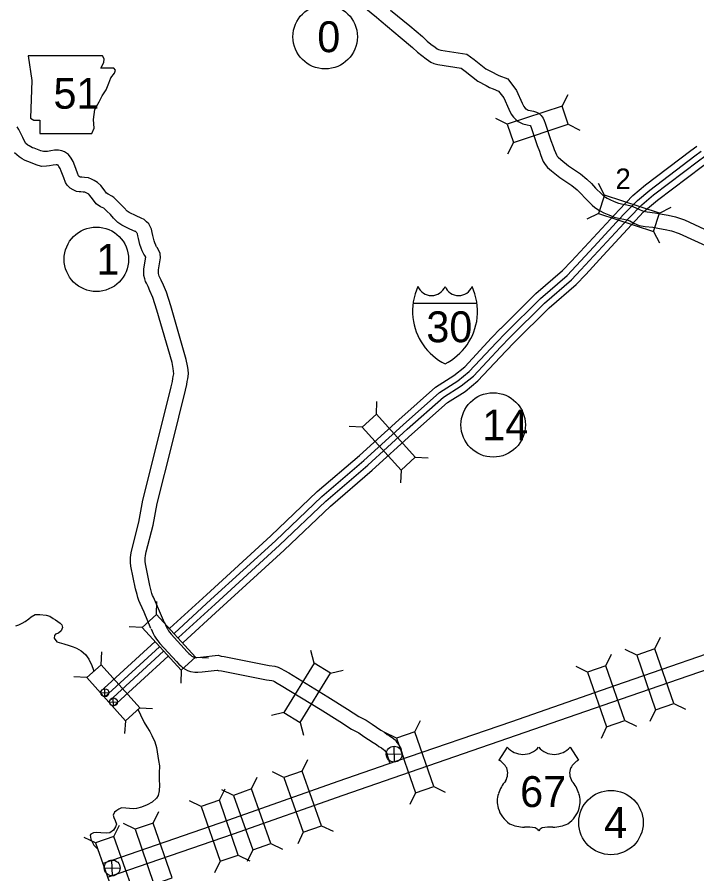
# Model space of a CAD drawing. Extents: x 1369979 to 1371646, y 379997 to 381064.
# Drawn here: x 1370115.6 to 1370224.5, y 380672.1 to 380809.4 of the extents above; entities that cross this region are included whole.
import ezdxf

# ---------------------------------------------------------------- set-up
doc = ezdxf.new("R2010")
doc.units = 0
doc.layers.add('R_Border Notes', color=7, linetype='Continuous')

msp = doc.modelspace()

# ---------------------------------------------------------------- linework, layer by layer
at = {"layer": 'R_Border Notes'}
for p, q in [((1370202.9, 380795.11), (1370203.82, 380796.96)), ((1370194.09, 380792.19), (1370192.25, 380793.11)), ((1370203.87, 380792.18), (1370205.72, 380791.25)), ((1370195.07, 380789.25), (1370194.14, 380787.41)), ((1370209.66, 380780.84), (1370208.72, 380782.68)), ((1370208.69, 380777.9), (1370206.85, 380776.96)), ((1370218.48, 380777.95), (1370220.32, 380778.88)), ((1370217.51, 380775.01), (1370218.45, 380773.17)), ((1370179, 380763.5), (1370189.24, 380763.5)), ((1370173.12, 380745.73), (1370173.22, 380747.79)), ((1370170.83, 380743.66), (1370168.77, 380743.76)), ((1370179.36, 380738.86), (1370181.42, 380738.76)), ((1370177.07, 380736.78), (1370176.97, 380734.72)), ((1370137.88, 380713.64), (1370137.97, 380715.7)), ((1370135.6, 380711.54), (1370133.53, 380711.63)), ((1370217.74, 380708.13), (1370218.65, 380709.99)), ((1370163.14, 380705.85), (1370162.65, 380707.86)), ((1370214.82, 380707.12), (1370212.97, 380708.03)), ((1370129.04, 380705.59), (1370129.16, 380707.65)), ((1370144.15, 380706.79), (1370146.21, 380706.7)), ((1370209.88, 380705.42), (1370210.78, 380707.27)), ((1370206.96, 380704.4), (1370205.1, 380705.3)), ((1370126.73, 380703.53), (1370124.67, 380703.64)), ((1370141.87, 380704.7), (1370141.78, 380702.64)), ((1370165.78, 380704.24), (1370167.78, 380704.73)), ((1370129, 380701.08), (1370130.27, 380701.11)), ((1370129.65, 380700.46), (1370129.62, 380701.73)), ((1370130.36, 380699.6), (1370131.63, 380699.63)), ((1370131.01, 380698.98), (1370130.98, 380700.25)), ((1370135.22, 380698.67), (1370137.28, 380698.55)), ((1370217.85, 380698.35), (1370216.95, 380696.5)), ((1370220.77, 380699.36), (1370222.63, 380698.46)), ((1370158.3, 380697.93), (1370156.3, 380697.45)), ((1370179.28, 380694.82), (1370180.19, 380696.67)), ((1370132.92, 380696.61), (1370132.8, 380694.55)), ((1370160.94, 380696.32), (1370161.43, 380694.32)), ((1370210, 380695.63), (1370209.11, 380693.78)), ((1370212.93, 380696.65), (1370214.78, 380695.75)), ((1370176.36, 380693.81), (1370174.5, 380694.71)), ((1370174.7, 380691.23), (1370177.25, 380691.29)), ((1370176.01, 380689.99), (1370175.95, 380692.53)), ((1370194.09, 380692.38), (1370192.74, 380690.29)), ((1370204.15, 380692.38), (1370205.5, 380690.29)), ((1370161.24, 380688.54), (1370162.13, 380690.4)), ((1370153.14, 380685.68), (1370154.03, 380687.54)), ((1370158.32, 380687.51), (1370156.46, 380688.4)), ((1370147.98, 380683.86), (1370148.89, 380685.72)), ((1370182.31, 380686.05), (1370184.16, 380685.14)), ((1370150.22, 380684.65), (1370148.36, 380685.54)), ((1370179.39, 380685.04), (1370178.48, 380683.18)), ((1370145.06, 380682.86), (1370143.2, 380683.76)), ((1370137.39, 380680.22), (1370138.29, 380682.07)), ((1370131.08, 380678.04), (1370131.97, 380679.9)), ((1370134.46, 380679.21), (1370132.61, 380680.12)), ((1370164.33, 380679.79), (1370166.19, 380678.9)), ((1370128.15, 380677.02), (1370126.3, 380677.92)), ((1370161.41, 380678.76), (1370160.52, 380676.9)), ((1370156.22, 380676.93), (1370158.09, 380676.04)), ((1370151, 380675.09), (1370152.85, 380674.18)), ((1370153.31, 380675.9), (1370152.42, 380674.04)), ((1370130.83, 380671.75), (1370130.77, 380674.29)), ((1370148.08, 380674.08), (1370147.17, 380672.23)), ((1370129.53, 380672.99), (1370132.07, 380673.05))]:
    msp.add_line(p, q, dxfattribs=at)
for points in [[(1370170.57, 380811.45), (1370173.14, 380809.33), (1370173.91, 380808.69), (1370176.96, 380806.16), (1370178.93, 380804.51), (1370179.72, 380803.75), (1370180.42, 380803.19), (1370181.12, 380802.66), (1370181.47, 380802.4), (1370181.82, 380802.14), (1370182.31, 380801.94), (1370182.96, 380801.75), (1370186.68, 380801.2), (1370187.35, 380800.7), (1370189.4, 380799.09), (1370190.72, 380798.41), (1370191.26, 380798.1), (1370191.85, 380797.85), (1370192.71, 380797.51)], [(1370175.41, 380810.49), (1370178.46, 380807.96), (1370180.49, 380806.26), (1370181.27, 380805.51), (1370181.86, 380805.04), (1370182.53, 380804.53), (1370182.87, 380804.28), (1370182.98, 380804.2), (1370183.09, 380804.15), (1370183.46, 380804.05), (1370187.6, 380803.43), (1370188.77, 380802.56), (1370190.67, 380801.07), (1370191.84, 380800.48), (1370192.31, 380800.2), (1370192.75, 380800.02), (1370194.18, 380799.45)], [(1370194.18, 380799.45), (1370195.57, 380797.6), (1370196.46, 380795.59), (1370196.73, 380795.04), (1370196.88, 380794.84), (1370197.03, 380794.68), (1370197.09, 380794.64), (1370197.44, 380794.45), (1370197.75, 380794.37), (1370198.3, 380794.28), (1370198.77, 380794.13), (1370199.18, 380793.91), (1370199.53, 380793.59), (1370199.84, 380793.16), (1370200.01, 380792.81), (1370200.15, 380792.39), (1370201.07, 380789.59), (1370201.45, 380788.65), (1370201.6, 380788.16), (1370201.81, 380787.65), (1370201.96, 380787.29), (1370202.09, 380787.07), (1370202.23, 380786.9), (1370202.67, 380786.52), (1370203.88, 380785.54), (1370205.83, 380784.25), (1370206.85, 380783.41), (1370207.57, 380782.71), (1370208.24, 380781.96), (1370209.26, 380780.98), (1370209.58, 380780.69), (1370210.07, 380780.36), (1370210.54, 380780.11), (1370211.21, 380779.84), (1370211.92, 380779.56), (1370212.63, 380779.4), (1370213.26, 380779.29), (1370213.96, 380779.12), (1370214.69, 380778.81), (1370215.36, 380778.46), (1370215.9, 380778.24), (1370216.51, 380778.14), (1370217.75, 380778.01), (1370218.9, 380777.81), (1370219.87, 380777.61), (1370221.02, 380777.35), (1370222.48, 380776.9), (1370228.11, 380774.27)], [(1370192.71, 380797.51), (1370193.54, 380796.41), (1370194.33, 380794.6), (1370194.72, 380793.82), (1370195.08, 380793.33), (1370195.45, 380792.94), (1370195.83, 380792.65), (1370196.6, 380792.25), (1370197.26, 380792.08), (1370197.75, 380792), (1370197.8, 380791.98), (1370197.82, 380791.95), (1370197.83, 380791.93), (1370197.92, 380791.66), (1370198.87, 380788.79), (1370199.24, 380787.86), (1370199.39, 380787.37), (1370199.64, 380786.76), (1370199.86, 380786.23), (1370200.16, 380785.73), (1370200.53, 380785.27), (1370201.17, 380784.72), (1370202.5, 380783.64), (1370204.43, 380782.37), (1370205.28, 380781.66), (1370205.89, 380781.08), (1370206.55, 380780.34), (1370207.67, 380779.25), (1370208.14, 380778.84), (1370208.86, 380778.35), (1370209.55, 380777.98), (1370210.34, 380777.67), (1370211.23, 380777.31), (1370212.17, 380777.1), (1370212.77, 380776.99), (1370213.23, 380776.88), (1370213.7, 380776.69), (1370214.38, 380776.34), (1370215.24, 380775.98), (1370216.19, 380775.81), (1370217.42, 380775.69), (1370218.46, 380775.5), (1370219.38, 380775.32), (1370220.42, 380775.09), (1370221.63, 380774.71), (1370227.1, 380772.16)], [(1370136.08, 380722.66), (1370136.08, 380722.67), (1370136.13, 380723.07), (1370136.27, 380723.66), (1370137.35, 380727.93), (1370138.01, 380731.44), (1370140.41, 380740.95), (1370142.54, 380749.58), (1370142.74, 380750.48), (1370142.84, 380750.97), (1370142.92, 380751.42), (1370143.01, 380752.18), (1370142.95, 380752.91), (1370142.86, 380753.47), (1370142.68, 380754.52), (1370140.2, 380763.12), (1370139.49, 380765.26), (1370139.01, 380766.41), (1370138.67, 380767.22), (1370138.4, 380767.72), (1370138.35, 380767.84), (1370138.27, 380768.07), (1370138.21, 380768.3), (1370138.2, 380768.51), (1370138.2, 380768.85), (1370138.54, 380770.79), (1370138.51, 380771.48), (1370138.28, 380771.95), (1370137.99, 380772.42), (1370137.9, 380772.56), (1370137.86, 380772.65), (1370137.81, 380772.8), (1370137.62, 380773.17), (1370137.51, 380773.53), (1370137.42, 380773.94), (1370137.33, 380774.36), (1370137.22, 380774.86), (1370137.09, 380775.38), (1370136.9, 380775.79), (1370136.66, 380776.21), (1370136.3, 380776.57), (1370135.94, 380776.92), (1370135.45, 380777.16), (1370134.63, 380777.51), (1370133.54, 380778.06), (1370133.21, 380778.29), (1370132.7, 380778.78), (1370132.21, 380779.32), (1370131.59, 380779.94), (1370131.05, 380780.43), (1370130.75, 380780.68), (1370130.16, 380780.99), (1370129.9, 380781.16), (1370129.54, 380781.66), (1370128.99, 380782.37), (1370128.46, 380782.87), (1370127.93, 380783.17), (1370127.49, 380783.39), (1370127, 380783.58), (1370126.39, 380783.66), (1370125.95, 380783.69), (1370125.73, 380783.7), (1370125.71, 380783.71), (1370125.66, 380783.73), (1370125.53, 380783.81), (1370125.43, 380783.91), (1370125.43, 380783.92), (1370125.25, 380784.38), (1370125.05, 380784.95), (1370124.82, 380785.54), (1370124.56, 380786.2), (1370124.21, 380786.74), (1370123.8, 380787.33), (1370123.16, 380787.75), (1370122.73, 380787.92), (1370122.2, 380788.05), (1370121.58, 380788.03), (1370120.99, 380787.93), (1370120.47, 380787.85), (1370120.12, 380787.81), (1370119.8, 380787.8), (1370119.38, 380787.93), (1370118.3, 380788.34), (1370118.04, 380788.44), (1370117.8, 380788.55), (1370117.5, 380788.71), (1370117.29, 380788.84), (1370116.98, 380789.12), (1370116.76, 380789.48), (1370116.49, 380790.05), (1370116.2, 380790.62), (1370115.84, 380791.35), (1370115.58, 380791.8)], [(1370212, 380778.5), (1370214.22, 380780.79), (1370216.23, 380782.47), (1370223.5, 380787.98), (1370224.46, 380788.68)], [(1370133.73, 380722.66), (1370133.72, 380722.78), (1370133.83, 380723.5), (1370133.99, 380724.21), (1370135.06, 380728.44), (1370135.72, 380731.94), (1370138.14, 380741.52), (1370140.25, 380750.12), (1370140.45, 380750.99), (1370140.54, 380751.43), (1370140.6, 380751.77), (1370140.66, 380752.22), (1370140.62, 380752.62), (1370140.55, 380753.07), (1370140.39, 380753.99), (1370137.96, 380762.42), (1370137.29, 380764.44), (1370136.86, 380765.5), (1370136.55, 380766.21), (1370136.28, 380766.71), (1370136.16, 380767), (1370136.03, 380767.4), (1370135.88, 380767.96), (1370135.86, 380768.46), (1370135.86, 380769.05), (1370136.18, 380770.89), (1370136.03, 380771.14), (1370135.86, 380771.38), (1370135.67, 380771.78), (1370135.63, 380771.91), (1370135.44, 380772.31), (1370135.25, 380772.91), (1370135.13, 380773.42), (1370135.04, 380773.86), (1370134.93, 380774.33), (1370134.87, 380774.61), (1370134.82, 380774.7), (1370134.78, 380774.77), (1370134.65, 380774.91), (1370134.57, 380774.98), (1370134.48, 380775.03), (1370133.64, 380775.38), (1370132.34, 380776.04), (1370131.72, 380776.47), (1370131.01, 380777.15), (1370130.51, 380777.71), (1370129.97, 380778.25), (1370129.51, 380778.67), (1370129.45, 380778.72), (1370128.95, 380778.97), (1370128.24, 380779.46), (1370127.67, 380780.25), (1370127.24, 380780.79), (1370127.05, 380780.98), (1370126.83, 380781.1), (1370126.54, 380781.24), (1370126.42, 380781.29), (1370126.15, 380781.32), (1370125.78, 380781.35), (1370125.52, 380781.37), (1370125.1, 380781.42), (1370124.55, 380781.66), (1370124.06, 380781.97), (1370123.6, 380782.42), (1370123.33, 380782.85), (1370123.04, 380783.58), (1370122.85, 380784.15), (1370122.64, 380784.69), (1370122.47, 380785.12), (1370122.27, 380785.43), (1370122.14, 380785.61), (1370122.06, 380785.66), (1370121.99, 380785.69), (1370121.96, 380785.7), (1370121.83, 380785.69), (1370121.37, 380785.61), (1370120.75, 380785.52), (1370120.28, 380785.48), (1370119.5, 380785.44), (1370118.63, 380785.71), (1370117.46, 380786.15), (1370117.11, 380786.28), (1370116.76, 380786.45), (1370116.36, 380786.66), (1370115.88, 380786.95), (1370115.14, 380787.62)], [(1370212.78, 380777.76), (1370214.96, 380780), (1370216.9, 380781.63), (1370224.15, 380787.12), (1370225.15, 380787.86)], [(1370213.49, 380777.09), (1370215.62, 380779.29), (1370217.51, 380780.86), (1370224.73, 380786.34), (1370225.76, 380787.1)], [(1370215.93, 380778.15), (1370218.17, 380780.02), (1370225.37, 380785.48), (1370226.49, 380786.3), (1370226.53, 380786.33)], [(1370193.05, 380759.47), (1370198.66, 380765.05), (1370202.96, 380768.75), (1370204.37, 380770.25), (1370207.16, 380773.27), (1370212, 380778.5)], [(1370193.8, 380758.71), (1370199.39, 380764.26), (1370203.7, 380767.98), (1370205.15, 380769.52), (1370207.94, 380772.54), (1370212.78, 380777.76)], [(1370195.25, 380757.25), (1370200.79, 380762.76), (1370205.12, 380766.49), (1370206.65, 380768.12), (1370209.45, 380771.15), (1370215.93, 380778.15)], [(1370194.49, 380758.01), (1370200.06, 380763.54), (1370204.38, 380767.27), (1370205.87, 380768.85), (1370208.66, 380771.88), (1370213.49, 380777.09)], [(1370140.02, 380711.43), (1370145.89, 380716.81), (1370156.23, 380726.22), (1370163.66, 380733.33), (1370170.4, 380739.11), (1370176.71, 380744.83), (1370182.61, 380750.08), (1370185.53, 380751.94), (1370187.27, 380753.34), (1370191.58, 380757.97), (1370193.03, 380759.45)], [(1370140.77, 380710.66), (1370146.62, 380716.01), (1370156.97, 380725.44), (1370164.38, 380732.53), (1370171.11, 380738.3), (1370177.42, 380744.03), (1370183.26, 380749.22), (1370186.16, 380751.06), (1370188, 380752.55), (1370192.36, 380757.23), (1370193.8, 380758.7)], [(1370141.41, 380709.92), (1370147.28, 380715.29), (1370157.63, 380724.72), (1370165.04, 380731.81), (1370171.75, 380737.57), (1370178.08, 380743.31), (1370183.85, 380748.44), (1370186.73, 380750.27), (1370188.67, 380751.84), (1370193.06, 380756.55), (1370194.5, 380758.02)], [(1370142.15, 380709.13), (1370148, 380714.5), (1370158.36, 380723.94), (1370165.76, 380731.01), (1370172.46, 380736.76), (1370178.8, 380742.51), (1370184.5, 380747.58), (1370187.36, 380749.39), (1370189.4, 380751.05), (1370193.84, 380755.81), (1370195.27, 380757.27)], [(1370137.01, 380711.4), (1370135.95, 380713.99), (1370135.28, 380715.41), (1370135.07, 380715.85), (1370134.93, 380716.33), (1370134.8, 380716.82), (1370134.56, 380717.73), (1370133.81, 380721.4), (1370133.76, 380721.99), (1370133.73, 380722.66)], [(1370139.18, 380712.29), (1370138.09, 380714.94), (1370137.4, 380716.4), (1370137.27, 380716.69), (1370137.18, 380716.98), (1370137.06, 380717.42), (1370136.85, 380718.26), (1370136.13, 380721.73), (1370136.1, 380722.14), (1370136.08, 380722.66)], [(1370115.35, 380711.8), (1370115.85, 380711.98), (1370116.39, 380712.24), (1370116.87, 380712.53), (1370117.45, 380712.96), (1370117.84, 380713.27), (1370118.47, 380713.62), (1370119.2, 380713.62), (1370120.24, 380713.54), (1370120.8, 380713.37), (1370121.37, 380712.98), (1370121.71, 380712.79), (1370122.49, 380712.26), (1370122.73, 380711.99), (1370122.84, 380711.56), (1370122.63, 380710.99), (1370122.23, 380710.63), (1370121.74, 380710.47), (1370121.54, 380710.26), (1370121.5, 380709.83), (1370121.94, 380709.25), (1370123.05, 380708.91), (1370123.9, 380708.64), (1370124.55, 380708.43), (1370125.08, 380708.25), (1370125.85, 380707.81), (1370126.55, 380707.24), (1370127.06, 380706.45), (1370127.53, 380705.47), (1370127.75, 380704.88), (1370127.87, 380704.48)], [(1370139.16, 380712.34), (1370139.49, 380711.62), (1370139.65, 380711.31), (1370139.83, 380711.03), (1370140, 380710.81), (1370140.25, 380710.46), (1370142.82, 380707.67), (1370143.1, 380707.37), (1370143.34, 380707.17), (1370143.56, 380706.98), (1370143.67, 380706.91), (1370143.83, 380706.83), (1370144, 380706.76), (1370144.22, 380706.72), (1370144.36, 380706.73), (1370144.96, 380706.79), (1370147.79, 380707.09), (1370148.25, 380706.98), (1370148.75, 380706.9), (1370149.29, 380706.79), (1370155.93, 380705.47), (1370156.88, 380705.33), (1370157.38, 380705.19), (1370157.84, 380704.98), (1370158.38, 380704.68), (1370159.1, 380704.26), (1370165.34, 380700.45), (1370168.52, 380698.48), (1370170.3, 380697.28), (1370171.47, 380696.7), (1370172.46, 380696.04), (1370173.85, 380695.08), (1370174.42, 380694.75), (1370174.87, 380694.42), (1370175.24, 380694.18), (1370175.64, 380693.9), (1370175.85, 380693.75), (1370176.17, 380693.49), (1370176.42, 380693.13), (1370176.69, 380692.8), (1370177.02, 380692.16), (1370177.14, 380691.58), (1370177.47, 380690.67)], [(1370137.03, 380711.36), (1370137.38, 380710.6), (1370137.61, 380710.14), (1370137.92, 380709.66), (1370138.12, 380709.41), (1370138.42, 380708.98), (1370141.1, 380706.08), (1370141.49, 380705.66), (1370141.82, 380705.39), (1370142.13, 380705.11), (1370142.51, 380704.87), (1370142.89, 380704.68), (1370143.36, 380704.49), (1370144.05, 380704.38), (1370144.51, 380704.39), (1370145.21, 380704.46), (1370147.64, 380704.72), (1370147.79, 380704.68), (1370148.33, 380704.59), (1370148.84, 380704.49), (1370155.54, 380703.16), (1370156.38, 380703.04), (1370156.57, 380702.98), (1370156.8, 380702.88), (1370157.21, 380702.65), (1370157.89, 380702.25), (1370164.11, 380698.45), (1370167.25, 380696.51), (1370169.12, 380695.25), (1370170.3, 380694.67), (1370171.14, 380694.1), (1370172.6, 380693.1), (1370173.14, 380692.79), (1370173.54, 380692.49), (1370173.92, 380692.24), (1370174.28, 380691.99), (1370174.43, 380691.88), (1370174.45, 380691.87), (1370174.55, 380691.72), (1370174.71, 380691.52), (1370174.79, 380691.36), (1370174.89, 380690.93), (1370175.25, 380689.92)], [(1370128.88, 380701.22), (1370137.69, 380709.29)], [(1370194.82, 380696.51), (1370211.47, 380702.3), (1370233.43, 380709.88)], [(1370129.57, 380700.39), (1370138.38, 380708.47)], [(1370130.25, 380699.69), (1370139.05, 380707.75)], [(1370195.59, 380694.3), (1370212.24, 380700.08), (1370234.2, 380707.66)], [(1370130.9, 380698.83), (1370139.75, 380706.94)], [(1370134.94, 380698.48), (1370135.35, 380697.58), (1370135.94, 380696.35), (1370136.38, 380695.62), (1370136.82, 380694.9), (1370137.16, 380694.23), (1370137.63, 380693.22), (1370137.89, 380692.33), (1370138.01, 380691.64), (1370138.2, 380690.22), (1370138.37, 380689.37), (1370138.32, 380688.21), (1370138.31, 380687.13), (1370138.36, 380686.3), (1370138.31, 380685.35), (1370138.15, 380684.62), (1370137.89, 380684.19), (1370137.22, 380683.58), (1370136.39, 380683.14), (1370135.51, 380682.77), (1370134.71, 380682.55), (1370134.21, 380682.48), (1370133.56, 380682.55), (1370133, 380682.62), (1370132.32, 380682.64), (1370131.85, 380682.45), (1370131.54, 380682.23), (1370131.18, 380681.95), (1370130.98, 380681.5), (1370131.07, 380681.1), (1370131.28, 380680.6), (1370131.49, 380680.04), (1370131.36, 380679.59), (1370131, 380679.05), (1370130.45, 380678.64), (1370129.95, 380678.61), (1370129.01, 380678.64), (1370128.29, 380678.69), (1370127.82, 380678.64), (1370127.6, 380678.55), (1370127.36, 380678.41), (1370127.28, 380678.26), (1370127.4, 380677.64), (1370127.64, 380677.08), (1370127.88, 380676.66), (1370128.26, 380676.27), (1370128.42, 380676.14)], [(1370129.24, 380673.75), (1370149.47, 380680.71), (1370167.01, 380686.9), (1370176.42, 380690.16), (1370194.82, 380696.51)], [(1370130.07, 380671.55), (1370150.24, 380678.49), (1370167.79, 380684.69), (1370177.18, 380687.95), (1370195.58, 380694.29)]]:
    msp.add_lwpolyline(points, dxfattribs=at)
for points in [[(1370117.37, 380803.15), (1370117.96, 380799.18), (1370117.7, 380793.17), (1370118.23, 380792.84), (1370119.22, 380792.84), (1370119.22, 380790.73), (1370127.55, 380790.73), (1370127.94, 380791.58), (1370127.81, 380792.97), (1370128.01, 380794.56), (1370128.74, 380795.81), (1370129.2, 380796.74), (1370129.86, 380797.73), (1370130.26, 380798.79), (1370130.59, 380799.65), (1370131.18, 380800.37), (1370131.31, 380800.84), (1370131.05, 380801.17), (1370129, 380801.17), (1370129.46, 380802.09), (1370129.53, 380802.69), (1370129.26, 380803.14)], [(1370202.9, 380795.11), (1370194.09, 380792.19), (1370195.07, 380789.25), (1370203.87, 380792.18)], [(1370208.69, 380777.9), (1370217.51, 380775.01), (1370218.48, 380777.95), (1370209.66, 380780.84)], [(1370170.83, 380743.66), (1370177.07, 380736.78), (1370179.36, 380738.86), (1370173.12, 380745.73)], [(1370135.6, 380711.54), (1370141.87, 380704.7), (1370144.15, 380706.79), (1370137.88, 380713.64)], [(1370220.77, 380699.36), (1370217.74, 380708.13), (1370214.82, 380707.12), (1370217.85, 380698.35)], [(1370126.73, 380703.53), (1370132.92, 380696.61), (1370135.22, 380698.67), (1370129.04, 380705.59)], [(1370163.14, 380705.85), (1370158.3, 380697.93), (1370160.94, 380696.32), (1370165.78, 380704.24)], [(1370206.96, 380704.4), (1370210, 380695.63), (1370212.93, 380696.65), (1370209.88, 380705.42)], [(1370182.31, 380686.05), (1370179.28, 380694.82), (1370176.36, 380693.81), (1370179.39, 380685.04)], [(1370158.32, 380687.51), (1370161.41, 380678.76), (1370164.33, 380679.79), (1370161.24, 380688.54)], [(1370156.22, 380676.93), (1370153.14, 380685.68), (1370150.22, 380684.65), (1370153.31, 380675.9)], [(1370145.06, 380682.86), (1370148.08, 380674.08), (1370151, 380675.09), (1370147.98, 380683.86)], [(1370134.46, 380679.21), (1370137.48, 380670.43), (1370140.4, 380671.44), (1370137.39, 380680.22)], [(1370128.15, 380677.02), (1370131.21, 380668.26), (1370134.14, 380669.28), (1370131.08, 380678.04)]]:
    msp.add_lwpolyline(points, close=True, dxfattribs=at)
for centre, radius in [((1370164.92, 380806.21), 5.16), ((1370128.27, 380770.55), 5.16), ((1370191.83, 380744.01), 5.16), ((1370129.64, 380701.09), 0.636), ((1370131, 380699.62), 0.636), ((1370175.98, 380691.26), 1.27), ((1370210.7, 380680.29), 5.16), ((1370130.8, 380673.02), 1.27)]:
    msp.add_circle(centre, radius, dxfattribs=at)
for centre, radius, start, end in [((1370188.51, 380762.17), 9.61, 155.2204, 185.7928), ((1370181.96, 380767.08), 2.34, 202.1459, 337.3414), ((1370186.28, 380767.08), 2.34, 202.6586, 337.8541), ((1370179.72, 380762.17), 9.61, 354.2072, 24.7796), ((1370188.34, 380762.25), 9.44, 186.3923, 243.4571), ((1370179.9, 380762.25), 9.44, 296.5429, 353.6077), ((1370196.61, 380694.5), 3.29, 220.075, 319.6701), ((1370201.63, 380694.5), 3.29, 220.3299, 319.925), ((1370190.98, 380687.26), 3.51, 30.7809, 59.9883), ((1370207.27, 380687.26), 3.51, 120.0117, 149.2191), ((1370191.75, 380688.18), 2.41, 328.8105, 21.2108), ((1370206.49, 380688.18), 2.41, 158.7892, 211.1895), ((1370198.05, 380683.25), 5.62, 138.9565, 162.6913), ((1370200.2, 380683.25), 5.62, 17.3087, 41.0435), ((1370196.19, 380683.71), 3.71, 160.9576, 197.3819), ((1370202.05, 380683.71), 3.71, 342.6181, 19.0424), ((1370196.8, 380683.72), 4.3, 195.1074, 237.1312), ((1370201.45, 380683.72), 4.3, 302.8688, 344.8926), ((1370196.88, 380685.07), 5.52, 244.0771, 269.5779), ((1370197, 380669.45), 10.1, 81.1942, 90.9539), ((1370198.27, 380678.51), 0.968, 28.0342, 72.9864), ((1370199.98, 380678.51), 0.968, 107.0136, 151.9658), ((1370201.24, 380669.45), 10.1, 89.0461, 98.8058), ((1370201.37, 380685.07), 5.52, 270.4221, 295.9229)]:
    msp.add_arc(centre, radius, start, end, dxfattribs=at)

# ---------------------------------------------------------------- texts
for s, height, p in [('0', 4.95, (1370163.66, 380803.74)), ('51', 4.95, (1370121.4, 380794.68)), ('2', 3.3, (1370211.42, 380781.8)), ('1', 4.95, (1370128.27, 380768.08)), ('30', 4.95, (1370181.13, 380757.26)), ('14', 4.95, (1370190.08, 380741.53)), ('67', 4.95, (1370196.15, 380682.78)), ('4', 4.95, (1370209.6, 380677.82))]:
    msp.add_text(s, height=height, dxfattribs=at).set_placement(p)

doc.saveas('drawing.dxf')
